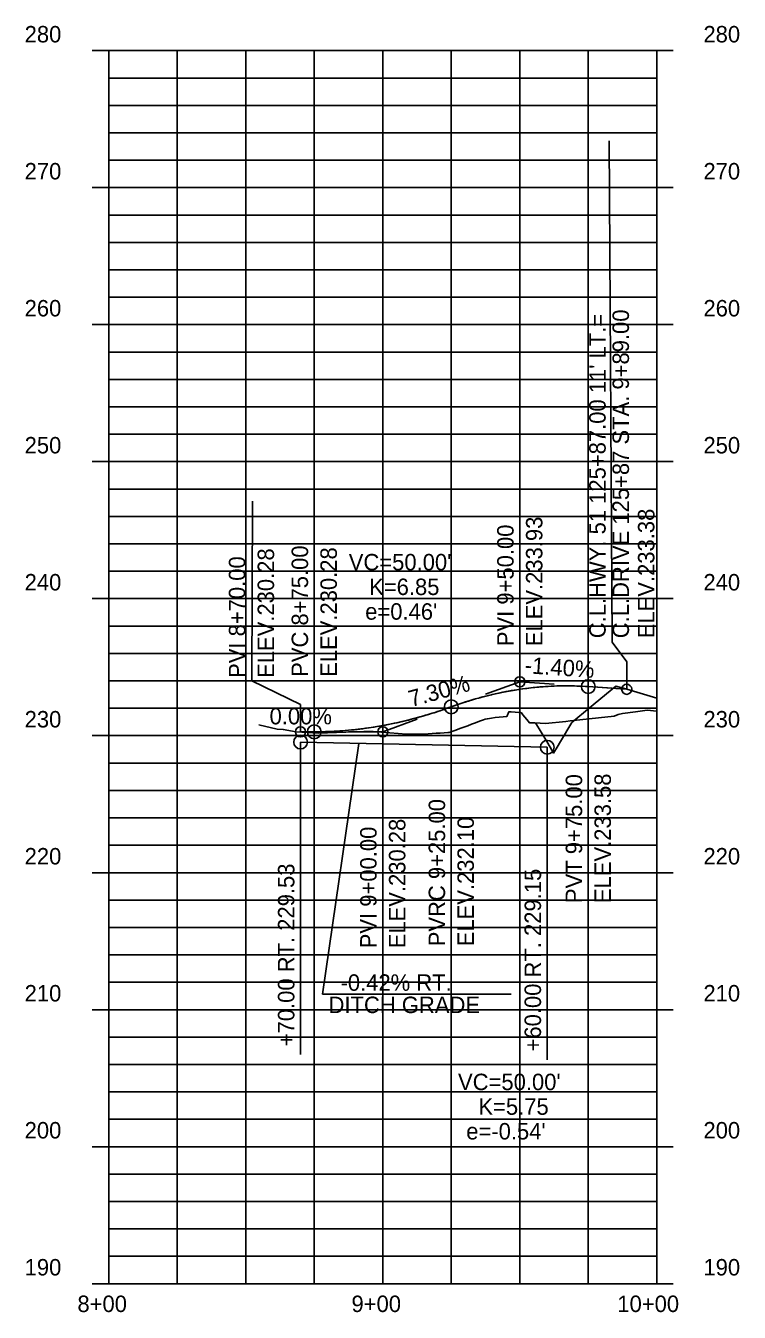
# Model space of a CAD drawing. Extents: x 921603 to 924670, y 1759276 to 1766491.
# Drawn here: x 921602.9 to 921863.2, y 1759275.5 to 1759745.1 of the extents above; entities that cross this region are included whole.
import ezdxf

# ---------------------------------------------------------------- set-up
doc = ezdxf.new("R2010")
doc.units = 0
for name, color, linetype in [('63', 7, 'Continuous'), ('R_Axis_Annotation', 7, 'Continuous'), ('R_Exist Surface', 7, 'Continuous'), ('R_Grid', 7, 'Continuous'), ('R_Grid Annot', 7, 'Continuous'), ('R_Grid_Minor', 7, 'Continuous'), ('R_Prop Surface', 7, 'Continuous'), ('R_Vert Alg', 7, 'Continuous'), ('R_Vert Alg Annot', 7, 'Continuous')]:
    doc.layers.add(name, color=color, linetype=linetype)

msp = doc.modelspace()

# ---------------------------------------------------------------- linework, layer by layer
at = {"layer": 'R_Exist Surface'}
msp.add_lwpolyline([(921687.92, 1759489.91), (921694.57, 1759488.36), (921696.85, 1759488.23), (921701.55, 1759487.32), (921709.75, 1759486.88), (921726.23, 1759487.46), (921729.68, 1759487.46), (921741.84, 1759486.54), (921745.42, 1759486.5), (921745.51, 1759486.51), (921749.75, 1759486.69), (921751.19, 1759486.75), (921752.63, 1759486.83), (921754.07, 1759486.91), (921755.51, 1759487), (921756.95, 1759487.09), (921757.3, 1759487.12), (921757.33, 1759487.14), (921758.39, 1759487.51), (921759.83, 1759488.02), (921761.27, 1759488.53), (921762.71, 1759489.05), (921764.15, 1759489.58), (921765.59, 1759490.12), (921767.03, 1759490.66), (921768.47, 1759491.2), (921769.91, 1759491.76), (921770.52, 1759491.99), (921771.35, 1759492.13), (921772.79, 1759492.35), (921774.22, 1759492.55), (921775.66, 1759492.72), (921777.1, 1759492.88), (921778.45, 1759493.01), (921778.54, 1759493.23), (921779.21, 1759494.72), (921779.98, 1759494.65), (921781.42, 1759494.54), (921782.86, 1759494.42), (921783.35, 1759494.37), (921783.76, 1759494.25), (921784.3, 1759493.63), (921785.74, 1759491.89), (921786.68, 1759490.7), (921787.18, 1759490.68), (921788.62, 1759490.61), (921792.49, 1759490.43), (921800.01, 1759491.18), (921801.49, 1759491.4), (921802.7, 1759491.55), (921817.53, 1759493.09), (921818.99, 1759493.64), (921820.63, 1759494.1), (921825.32, 1759494.64), (921829.66, 1759495.23), (921833.15, 1759494.85)], dxfattribs=at)
at = {"layer": 'R_Grid'}
for p, q in [((921633.15, 1759285.97), (921633.15, 1759735.97)), ((921633.15, 1759735.97), (921833.15, 1759735.97)), ((921633.15, 1759735.97), (921833.15, 1759735.97)), ((921733.15, 1759285.97), (921733.15, 1759735.97)), ((921833.15, 1759285.97), (921833.15, 1759735.97)), ((921633.15, 1759685.97), (921833.15, 1759685.97)), ((921633.15, 1759635.97), (921833.15, 1759635.97)), ((921633.15, 1759585.97), (921833.15, 1759585.97)), ((921633.15, 1759535.97), (921833.15, 1759535.97)), ((921633.15, 1759485.97), (921833.15, 1759485.97)), ((921633.15, 1759435.97), (921833.15, 1759435.97)), ((921633.15, 1759385.97), (921833.15, 1759385.97)), ((921633.15, 1759335.97), (921833.15, 1759335.97)), ((921633.15, 1759285.97), (921833.15, 1759285.97))]:
    msp.add_line(p, q, dxfattribs=at)
at = {"layer": 'R_Grid Annot'}
for p, q in [((921627.15, 1759735.97), (921633.15, 1759735.97)), ((921627.15, 1759735.97), (921633.15, 1759735.97)), ((921839.15, 1759735.97), (921833.15, 1759735.97)), ((921839.15, 1759735.97), (921833.15, 1759735.97)), ((921633.15, 1759725.97), (921636.15, 1759725.97)), ((921833.15, 1759725.97), (921830.15, 1759725.97)), ((921633.15, 1759715.97), (921636.15, 1759715.97)), ((921833.15, 1759715.97), (921830.15, 1759715.97)), ((921633.15, 1759705.97), (921636.15, 1759705.97)), ((921833.15, 1759705.97), (921830.15, 1759705.97)), ((921633.15, 1759695.97), (921636.15, 1759695.97)), ((921833.15, 1759695.97), (921830.15, 1759695.97)), ((921627.15, 1759685.97), (921633.15, 1759685.97)), ((921839.15, 1759685.97), (921833.15, 1759685.97)), ((921633.15, 1759675.97), (921636.15, 1759675.97)), ((921833.15, 1759675.97), (921830.15, 1759675.97)), ((921633.15, 1759665.97), (921636.15, 1759665.97)), ((921833.15, 1759665.97), (921830.15, 1759665.97)), ((921633.15, 1759655.97), (921636.15, 1759655.97)), ((921833.15, 1759655.97), (921830.15, 1759655.97)), ((921633.15, 1759645.97), (921636.15, 1759645.97)), ((921833.15, 1759645.97), (921830.15, 1759645.97)), ((921627.15, 1759635.97), (921633.15, 1759635.97)), ((921839.15, 1759635.97), (921833.15, 1759635.97)), ((921633.15, 1759625.97), (921636.15, 1759625.97)), ((921833.15, 1759625.97), (921830.15, 1759625.97)), ((921633.15, 1759615.97), (921636.15, 1759615.97)), ((921833.15, 1759615.97), (921830.15, 1759615.97)), ((921633.15, 1759605.97), (921636.15, 1759605.97)), ((921833.15, 1759605.97), (921830.15, 1759605.97)), ((921633.15, 1759595.97), (921636.15, 1759595.97)), ((921833.15, 1759595.97), (921830.15, 1759595.97)), ((921627.15, 1759585.97), (921633.15, 1759585.97)), ((921839.15, 1759585.97), (921833.15, 1759585.97)), ((921633.15, 1759575.97), (921636.15, 1759575.97)), ((921833.15, 1759575.97), (921830.15, 1759575.97)), ((921633.15, 1759565.97), (921636.15, 1759565.97)), ((921833.15, 1759565.97), (921830.15, 1759565.97)), ((921633.15, 1759555.97), (921636.15, 1759555.97)), ((921833.15, 1759555.97), (921830.15, 1759555.97)), ((921633.15, 1759545.97), (921636.15, 1759545.97)), ((921833.15, 1759545.97), (921830.15, 1759545.97)), ((921627.15, 1759535.97), (921633.15, 1759535.97)), ((921839.15, 1759535.97), (921833.15, 1759535.97)), ((921633.15, 1759525.97), (921636.15, 1759525.97)), ((921833.15, 1759525.97), (921830.15, 1759525.97)), ((921633.15, 1759515.97), (921636.15, 1759515.97)), ((921833.15, 1759515.97), (921830.15, 1759515.97)), ((921633.15, 1759505.97), (921636.15, 1759505.97)), ((921833.15, 1759505.97), (921830.15, 1759505.97)), ((921633.15, 1759495.97), (921636.15, 1759495.97)), ((921833.15, 1759495.97), (921830.15, 1759495.97)), ((921627.15, 1759485.97), (921633.15, 1759485.97)), ((921839.15, 1759485.97), (921833.15, 1759485.97)), ((921633.15, 1759475.97), (921636.15, 1759475.97)), ((921833.15, 1759475.97), (921830.15, 1759475.97)), ((921633.15, 1759465.97), (921636.15, 1759465.97)), ((921833.15, 1759465.97), (921830.15, 1759465.97)), ((921633.15, 1759455.97), (921636.15, 1759455.97)), ((921833.15, 1759455.97), (921830.15, 1759455.97)), ((921633.15, 1759445.97), (921636.15, 1759445.97)), ((921833.15, 1759445.97), (921830.15, 1759445.97)), ((921627.15, 1759435.97), (921633.15, 1759435.97)), ((921839.15, 1759435.97), (921833.15, 1759435.97)), ((921633.15, 1759425.97), (921636.15, 1759425.97)), ((921833.15, 1759425.97), (921830.15, 1759425.97)), ((921633.15, 1759415.97), (921636.15, 1759415.97)), ((921833.15, 1759415.97), (921830.15, 1759415.97)), ((921633.15, 1759405.97), (921636.15, 1759405.97)), ((921833.15, 1759405.97), (921830.15, 1759405.97)), ((921633.15, 1759395.97), (921636.15, 1759395.97)), ((921833.15, 1759395.97), (921830.15, 1759395.97)), ((921627.15, 1759385.97), (921633.15, 1759385.97)), ((921839.15, 1759385.97), (921833.15, 1759385.97)), ((921633.15, 1759375.97), (921636.15, 1759375.97)), ((921833.15, 1759375.97), (921830.15, 1759375.97)), ((921633.15, 1759365.97), (921636.15, 1759365.97)), ((921833.15, 1759365.97), (921830.15, 1759365.97)), ((921633.15, 1759355.97), (921636.15, 1759355.97)), ((921833.15, 1759355.97), (921830.15, 1759355.97)), ((921633.15, 1759345.97), (921636.15, 1759345.97)), ((921833.15, 1759345.97), (921830.15, 1759345.97)), ((921627.15, 1759335.97), (921633.15, 1759335.97)), ((921839.15, 1759335.97), (921833.15, 1759335.97)), ((921633.15, 1759325.97), (921636.15, 1759325.97)), ((921833.15, 1759325.97), (921830.15, 1759325.97)), ((921633.15, 1759315.97), (921636.15, 1759315.97)), ((921833.15, 1759315.97), (921830.15, 1759315.97)), ((921633.15, 1759305.97), (921636.15, 1759305.97)), ((921833.15, 1759305.97), (921830.15, 1759305.97)), ((921633.15, 1759295.97), (921636.15, 1759295.97)), ((921833.15, 1759295.97), (921830.15, 1759295.97)), ((921627.15, 1759285.97), (921633.15, 1759285.97)), ((921839.15, 1759285.97), (921833.15, 1759285.97))]:
    msp.add_line(p, q, dxfattribs=at)
at = {"layer": 'R_Grid_Minor'}
for p, q in [((921658.15, 1759285.97), (921658.15, 1759735.97)), ((921683.15, 1759285.97), (921683.15, 1759735.97)), ((921708.15, 1759285.97), (921708.15, 1759735.97)), ((921758.15, 1759285.97), (921758.15, 1759735.97)), ((921783.15, 1759285.97), (921783.15, 1759735.97)), ((921808.15, 1759285.97), (921808.15, 1759735.97)), ((921633.15, 1759725.97), (921833.15, 1759725.97)), ((921633.15, 1759715.97), (921833.15, 1759715.97)), ((921633.15, 1759705.97), (921833.15, 1759705.97)), ((921633.15, 1759695.97), (921833.15, 1759695.97)), ((921633.15, 1759675.97), (921833.15, 1759675.97)), ((921633.15, 1759665.97), (921833.15, 1759665.97)), ((921633.15, 1759655.97), (921833.15, 1759655.97)), ((921633.15, 1759645.97), (921833.15, 1759645.97)), ((921633.15, 1759625.97), (921833.15, 1759625.97)), ((921633.15, 1759615.97), (921833.15, 1759615.97)), ((921633.15, 1759605.97), (921833.15, 1759605.97)), ((921633.15, 1759595.97), (921833.15, 1759595.97)), ((921633.15, 1759575.97), (921833.15, 1759575.97)), ((921633.15, 1759565.97), (921833.15, 1759565.97)), ((921633.15, 1759555.97), (921833.15, 1759555.97)), ((921633.15, 1759545.97), (921833.15, 1759545.97)), ((921633.15, 1759525.97), (921833.15, 1759525.97)), ((921633.15, 1759515.97), (921833.15, 1759515.97)), ((921633.15, 1759505.97), (921833.15, 1759505.97)), ((921633.15, 1759495.97), (921833.15, 1759495.97)), ((921633.15, 1759475.97), (921833.15, 1759475.97)), ((921633.15, 1759465.97), (921833.15, 1759465.97)), ((921633.15, 1759455.97), (921833.15, 1759455.97)), ((921633.15, 1759445.97), (921833.15, 1759445.97)), ((921633.15, 1759425.97), (921833.15, 1759425.97)), ((921633.15, 1759415.97), (921833.15, 1759415.97)), ((921633.15, 1759405.97), (921833.15, 1759405.97)), ((921633.15, 1759395.97), (921833.15, 1759395.97)), ((921633.15, 1759375.97), (921833.15, 1759375.97)), ((921633.15, 1759365.97), (921833.15, 1759365.97)), ((921633.15, 1759355.97), (921833.15, 1759355.97)), ((921633.15, 1759345.97), (921833.15, 1759345.97)), ((921633.15, 1759325.97), (921833.15, 1759325.97)), ((921633.15, 1759315.97), (921833.15, 1759315.97)), ((921633.15, 1759305.97), (921833.15, 1759305.97)), ((921633.15, 1759295.97), (921833.15, 1759295.97))]:
    msp.add_line(p, q, dxfattribs=at)
at = {"layer": 'R_Prop Surface'}
for points in [[(921703.15, 1759487.37), (921708.15, 1759487.37), (921713.15, 1759487.46), (921718.15, 1759487.73), (921723.15, 1759488.19), (921728.15, 1759488.83), (921733.15, 1759489.65), (921738.15, 1759490.65), (921743.15, 1759491.84), (921748.15, 1759493.21), (921749.75, 1759493.71), (921751.19, 1759494.15), (921752.63, 1759494.6), (921753.05, 1759494.73), (921753.15, 1759494.76), (921753.15, 1759494.76), (921753.25, 1759494.8), (921754.07, 1759495.08), (921755.51, 1759495.58), (921756.95, 1759496.08), (921758.08, 1759496.47), (921758.15, 1759496.49), (921758.2, 1759496.51), (921758.39, 1759496.58), (921759.83, 1759497.07), (921761.27, 1759497.56), (921762.71, 1759498.06), (921763.07, 1759498.18), (921763.15, 1759498.21), (921763.15, 1759498.21), (921763.25, 1759498.24), (921764.15, 1759498.51), (921765.59, 1759498.94), (921767.03, 1759499.37), (921768.06, 1759499.68), (921768.15, 1759499.71), (921768.15, 1759499.71), (921768.15, 1759499.71), (921768.36, 1759499.77), (921768.47, 1759499.8), (921768.63, 1759499.84), (921769.05, 1759499.96), (921769.05, 1759499.96), (921769.18, 1759499.99), (921769.91, 1759500.17), (921771.35, 1759500.54), (921772.79, 1759500.9), (921773.07, 1759500.97), (921773.15, 1759500.99), (921773.15, 1759500.99), (921773.24, 1759501.01), (921774.22, 1759501.22), (921775.66, 1759501.53), (921777.1, 1759501.83), (921778.05, 1759502.03), (921778.15, 1759502.05), (921778.22, 1759502.07), (921778.54, 1759502.12), (921779.98, 1759502.36), (921781.42, 1759502.61), (921782.86, 1759502.85), (921783.09, 1759502.89), (921783.15, 1759502.9), (921783.15, 1759502.9), (921783.23, 1759502.91), (921784.3, 1759503.05), (921785.74, 1759503.23), (921787.18, 1759503.41), (921788.05, 1759503.52), (921788.15, 1759503.53), (921788.15, 1759503.53), (921788.48, 1759503.56), (921788.62, 1759503.57), (921793.15, 1759503.94), (921794.65, 1759504.02), (921794.82, 1759504.03), (921798.15, 1759504.13), (921803.15, 1759504.11), (921808.15, 1759503.87), (921813.15, 1759503.52), (921818.15, 1759503.17), (921822.15, 1759502.89)], [(921788.89, 1759490.6), (921792.97, 1759483.81), (921794.19, 1759481.77), (921795.48, 1759479.62), (921796.79, 1759481.81), (921798.04, 1759483.89), (921802.15, 1759490.74), (921808.6, 1759496.12), (921818.15, 1759504.07), (921822.15, 1759502.89), (921833.15, 1759499.64)]]:
    msp.add_lwpolyline(points, dxfattribs=at)
at = {"layer": 'R_Vert Alg'}
for p, q in [((921808.15, 1759503.87), (921822.15, 1759502.89)), ((921703.15, 1759487.37), (921708.15, 1759487.37)), ((921703.15, 1759483.62), (921793.15, 1759481.72))]:
    msp.add_line(p, q, dxfattribs=at)
for points in [[(921758.15, 1759496.49), (921759.19, 1759496.87), (921760.23, 1759497.24), (921761.27, 1759497.59), (921762.31, 1759497.94), (921763.36, 1759498.28), (921764.4, 1759498.61), (921765.44, 1759498.92), (921766.48, 1759499.23), (921767.52, 1759499.53), (921768.56, 1759499.82), (921769.61, 1759500.11), (921770.65, 1759500.38), (921771.69, 1759500.64), (921772.73, 1759500.89), (921773.77, 1759501.14), (921774.81, 1759501.37), (921775.86, 1759501.59), (921776.9, 1759501.81), (921777.94, 1759502.01), (921778.98, 1759502.21), (921780.02, 1759502.4), (921781.06, 1759502.57), (921782.11, 1759502.74), (921784.19, 1759503.05), (921785.23, 1759503.19), (921786.27, 1759503.32), (921787.31, 1759503.44), (921788.36, 1759503.55), (921789.4, 1759503.65), (921790.44, 1759503.75), (921791.48, 1759503.83), (921792.52, 1759503.9), (921793.56, 1759503.97), (921794.61, 1759504.02), (921795.65, 1759504.06), (921796.69, 1759504.1), (921797.73, 1759504.13), (921798.77, 1759504.14), (921799.81, 1759504.15), (921800.86, 1759504.15), (921801.9, 1759504.14), (921802.94, 1759504.12), (921803.98, 1759504.09), (921805.02, 1759504.05), (921806.06, 1759504), (921807.11, 1759503.94), (921808.15, 1759503.87)], [(921708.15, 1759487.37), (921709.19, 1759487.37), (921710.23, 1759487.39), (921711.27, 1759487.41), (921712.31, 1759487.43), (921713.36, 1759487.47), (921714.4, 1759487.51), (921715.44, 1759487.56), (921716.48, 1759487.62), (921717.52, 1759487.69), (921718.56, 1759487.77), (921719.61, 1759487.85), (921720.65, 1759487.94), (921721.69, 1759488.04), (921722.73, 1759488.15), (921723.77, 1759488.26), (921724.81, 1759488.38), (921725.86, 1759488.51), (921726.9, 1759488.65), (921727.94, 1759488.8), (921728.98, 1759488.95), (921730.02, 1759489.12), (921731.06, 1759489.29), (921732.11, 1759489.46), (921734.19, 1759489.84), (921735.23, 1759490.05), (921736.27, 1759490.26), (921737.31, 1759490.47), (921738.36, 1759490.7), (921739.4, 1759490.93), (921740.44, 1759491.18), (921741.48, 1759491.43), (921742.52, 1759491.68), (921743.56, 1759491.95), (921744.61, 1759492.22), (921745.65, 1759492.5), (921746.69, 1759492.79), (921747.73, 1759493.09), (921748.77, 1759493.39), (921749.81, 1759493.71), (921750.86, 1759494.03), (921751.9, 1759494.36), (921752.94, 1759494.69), (921753.98, 1759495.04), (921755.02, 1759495.39), (921756.06, 1759495.75), (921757.11, 1759496.12), (921758.15, 1759496.49)]]:
    msp.add_lwpolyline(points, dxfattribs=at)
at = {"layer": 'R_Vert Alg Annot'}
for p, q in [((921783.15, 1759515.62), (921783.15, 1759587.62)), ((921708.15, 1759497.37), (921708.15, 1759572.88)), ((921783.15, 1759505.62), (921783.15, 1759515.62)), ((921822.15, 1759502.89), (921822.15, 1759512.89)), ((921770.65, 1759501.06), (921783.15, 1759505.62)), ((921783.15, 1759505.62), (921795.65, 1759504.74)), ((921808.15, 1759503.87), (921808.15, 1759493.87)), ((921703.15, 1759487.37), (921703.15, 1759497.37)), ((921708.15, 1759487.37), (921708.15, 1759497.37)), ((921758.15, 1759496.49), (921758.15, 1759406.1)), ((921733.15, 1759487.37), (921745.65, 1759491.93)), ((921808.15, 1759493.87), (921808.15, 1759421.87)), ((921720.65, 1759487.37), (921733.15, 1759487.37)), ((921733.15, 1759487.37), (921733.15, 1759477.37)), ((921703.15, 1759483.62), (921703.15, 1759453.62)), ((921793.15, 1759481.72), (921793.15, 1759451.72)), ((921733.15, 1759477.37), (921733.15, 1759405.37)), ((921703.15, 1759453.62), (921703.15, 1759369.62)), ((921793.15, 1759451.72), (921793.15, 1759367.72))]:
    msp.add_line(p, q, dxfattribs=at)
for points in [[(921822.15, 1759512.89), (921816.84, 1759520.07), (921815.72, 1759703.06)], [(921703.15, 1759497.37), (921685.35, 1759505.97), (921685.61, 1759571.5)], [(921724.39, 1759483.17), (921711.18, 1759391.66), (921780, 1759391.66)]]:
    msp.add_lwpolyline(points, dxfattribs=at)
for centre, radius in [((921783.15, 1759505.62), 1.85), ((921808.15, 1759503.87), 2.5), ((921822.15, 1759502.89), 1.85), ((921758.15, 1759496.49), 2.5), ((921703.15, 1759487.37), 1.85), ((921708.15, 1759487.37), 2.5), ((921733.15, 1759487.37), 1.85), ((921703.15, 1759483.62), 2.5), ((921793.15, 1759481.72), 2.5)]:
    msp.add_circle(centre, radius, dxfattribs=at)

# ---------------------------------------------------------------- texts
at = {"layer": '63'}
msp.add_text('-', height=0.0001, dxfattribs=at).set_placement((921633.15, 1759285.97))
at = {"layer": 'R_Axis_Annotation'}
for s, p in [('280', (921602.48, 1759738.97)), ('280', (921602.48, 1759738.97)), ('280', (921850.16, 1759738.97)), ('280', (921850.16, 1759738.97)), ('270', (921602.48, 1759688.97)), ('270', (921850.16, 1759688.97)), ('260', (921602.48, 1759638.97)), ('260', (921850.16, 1759638.97)), ('250', (921602.48, 1759588.97)), ('250', (921850.16, 1759588.97)), ('240', (921602.48, 1759538.97)), ('240', (921850.16, 1759538.97)), ('230', (921602.48, 1759488.97)), ('230', (921850.16, 1759488.97)), ('220', (921602.48, 1759438.97)), ('220', (921850.16, 1759438.97)), ('210', (921602.48, 1759388.97)), ('210', (921850.16, 1759388.97)), ('200', (921602.48, 1759338.97)), ('200', (921850.16, 1759338.97)), ('190', (921602.48, 1759288.97)), ('190', (921850.16, 1759288.97)), ('8+00', (921621.74, 1759275.62)), ('9+00', (921721.74, 1759275.62)), ('10+00', (921818.74, 1759275.62))]:
    msp.add_text(s, height=6, dxfattribs=at).set_placement(p)
at = {"layer": 'R_Vert Alg Annot'}
for s, rotation, p in [("C.L.HWY. 51 125+87.00 11' LT.= ", 90, (921814.48, 1759521.52)), ('C.L.DRIVE 125+87 STA. 9+89.00 ', 90, (921822.99, 1759521.52)), ('ELEV.233.38', 90, (921832.26, 1759521.52)), ('PVI 9+50.00', 90, (921780.9, 1759518.62)), ('ELEV.233.93', 90, (921791.4, 1759518.62)), ('ELEV.230.28', 90, (921693.49, 1759507.04)), ('PVC 8+75.00', 90, (921705.9, 1759507.43)), ('ELEV.230.28', 90, (921716.4, 1759507.43)), ('PVI 8+70.00', 90, (921682.99, 1759507.04)), ('-1.40%', 355.9958, (921784.82, 1759508.79)), ('7.30%', 15.4326, (921743.53, 1759496.38)), ('0.00%', 360, (921691.85, 1759490.09)), ('PVT 9+75.00', 90, (921805.9, 1759424.87)), ('ELEV.233.58', 90, (921816.4, 1759424.87)), ('PVRC 9+25.00', 90, (921755.9, 1759409.1)), ('ELEV.230.28', 90, (921741.4, 1759408.37)), ('ELEV.232.10', 90, (921766.4, 1759409.1)), ('PVI 9+00.00', 90, (921730.9, 1759408.37)), ('+70.00 RT. 229.53', 90, (921700.9, 1759372.62)), ('+60.00 RT. 229.15', 90, (921790.9, 1759370.72))]:
    msp.add_text(s, height=6, rotation=rotation, dxfattribs=at).set_placement(p)
for s, p in [("VC=50.00'", (921720.74, 1759546.29)), ('K=6.85', (921728.18, 1759537.29)), ("e=0.46'", (921726.74, 1759528.29)), ('-0.42% RT.', (921717.74, 1759392.86)), ('DITCH GRADE', (921713.37, 1759384.73)), ("VC=50.00'", (921760.61, 1759356.6)), ('K=5.75', (921768.05, 1759347.6)), ("e=-0.54'", (921763.61, 1759338.6))]:
    msp.add_text(s, height=6, dxfattribs=at).set_placement(p)

doc.saveas('drawing.dxf')
